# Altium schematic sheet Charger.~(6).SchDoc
size A3; SheetNumber: 2; SheetTotal: 2
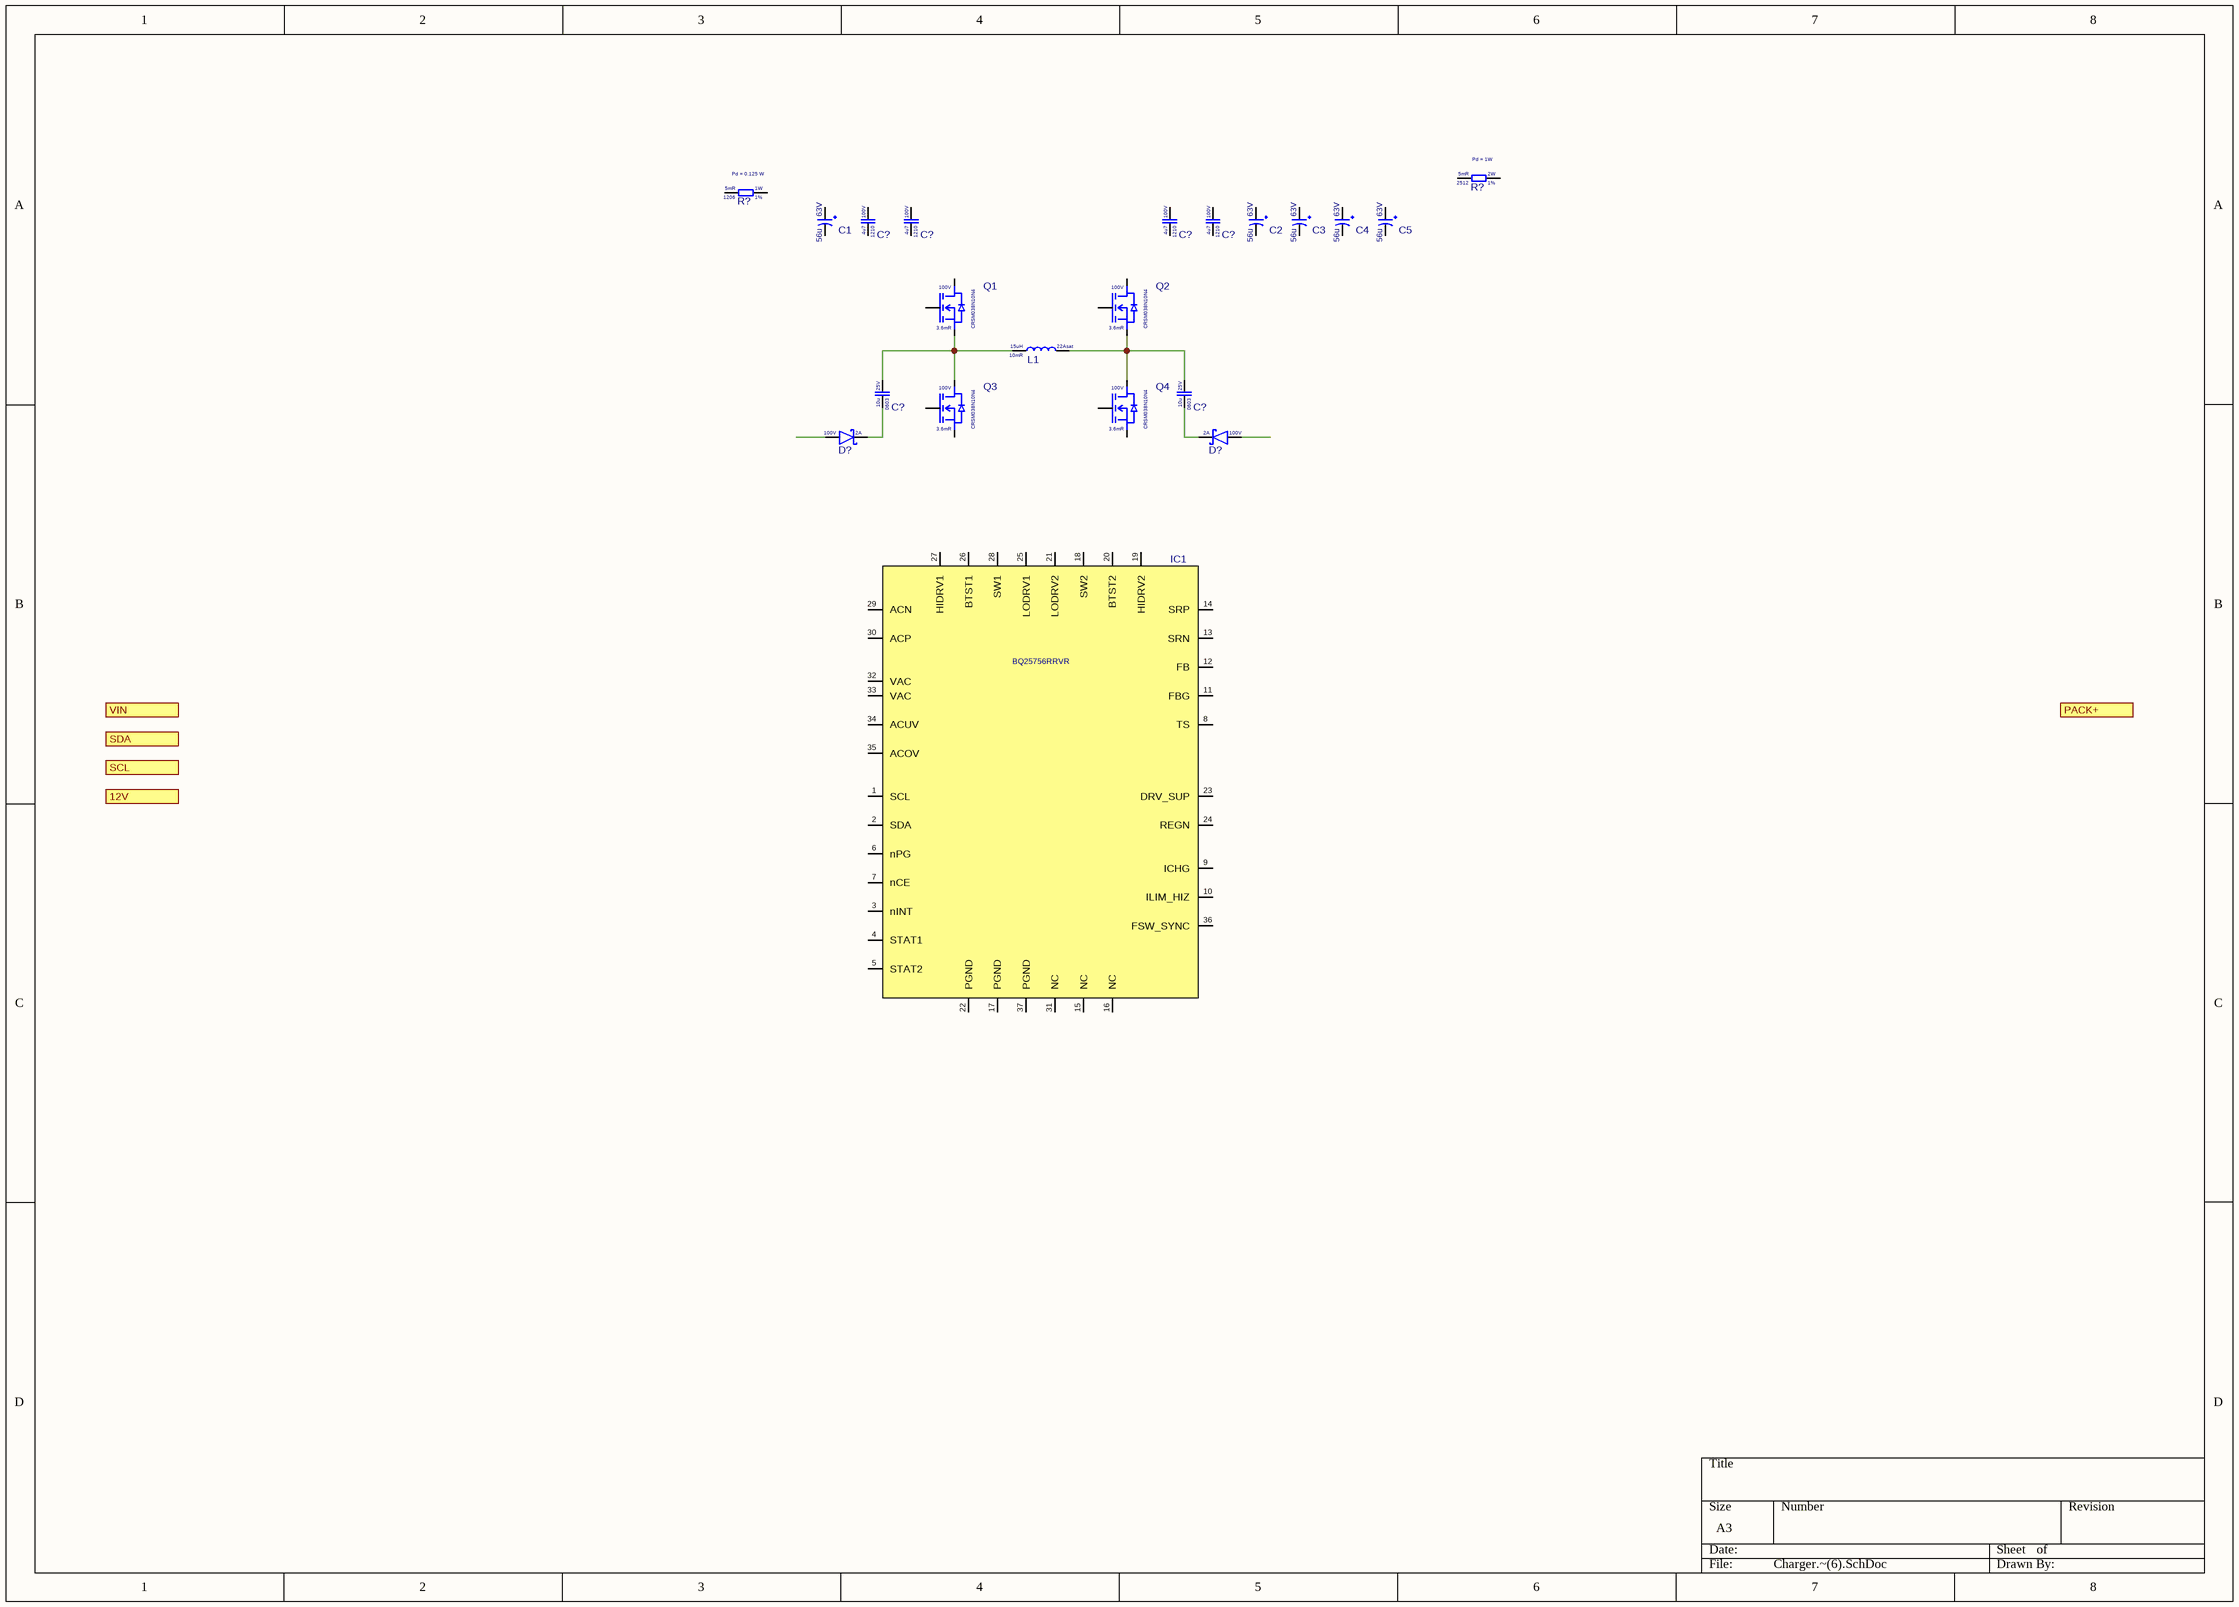
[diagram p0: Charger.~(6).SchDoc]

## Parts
(Parts that share a designator on the sheet are numbered #1, #2 ... from top to bottom, then left to right.)
C1  Voltage Rating: 63V  Capacitance: 56u  [CAP_SMD_10X10.2]  (hidden comment: EEHZA1J560P)
C2  Voltage Rating: 63V  Capacitance: 56u  [CAP_SMD_10X10.2]  (hidden comment: EEHZA1J560P)
C3  Voltage Rating: 63V  Capacitance: 56u  [CAP_SMD_10X10.2]  (hidden comment: EEHZA1J560P)
C4  Voltage Rating: 63V  Capacitance: 56u  [CAP_SMD_10X10.2]  (hidden comment: EEHZA1J560P)
C5  Voltage Rating: 63V  Capacitance: 56u  [CAP_SMD_10X10.2]  (hidden comment: EEHZA1J560P)
C?#1  Voltage Rating: 100V  Case Code (Imperial): 1210  Capacitance: 4u7  [CAP_1210]  (hidden comment: HMK325C7475KN-TE)
C?#2  Voltage Rating: 100V  Case Code (Imperial): 1210  Capacitance: 4u7  [CAP_1210]  (hidden comment: HMK325C7475KN-TE)
C?#3  Voltage Rating: 100V  Case Code (Imperial): 1210  Capacitance: 4u7  [CAP_1210]  (hidden comment: HMK325C7475KN-TE)
C?#4  Voltage Rating: 100V  Case Code (Imperial): 1210  Capacitance: 4u7  [CAP_1210]  (hidden comment: HMK325C7475KN-TE)
C?#5  Voltage Rating: 25V  Case Code (Imperial): 0603  Capacitance: 10u  [CAP 0603]  (hidden comment: CL10A106MA8NRNC)
C?#6  Voltage Rating: 25V  Case Code (Imperial): 0603  Capacitance: 10u  [CAP 0603]  (hidden comment: CL10A106MA8NRNC)
D?#1  Forward Current: 2A  Reverse Voltage: 100V  [SMAF]  (hidden comment: SS210F)
D?#2  Forward Current: 2A  Reverse Voltage: 100V  [SMAF]  (hidden comment: SS210F)
IC1  BQ25756RRVR  [VQFN-36(5x6)]
L1  Resistance: 10mR  Saturation current: 22Asat  Inductance: 15uH  [MTF1810-150M]  (hidden comment: MTF1810-150M)
Q1  Rds: 3.6mR  Voltage: 100V  [DFN-8 (5x6)]  (hidden comment: CRSM038N10N4)
Q2  Rds: 3.6mR  Voltage: 100V  [DFN-8 (5x6)]  (hidden comment: CRSM038N10N4)
Q3  Rds: 3.6mR  Voltage: 100V  [DFN-8 (5x6)]  (hidden comment: CRSM038N10N4)
Q4  Rds: 3.6mR  Voltage: 100V  [DFN-8 (5x6)]  (hidden comment: CRSM038N10N4)
R?#1  Pd = 1W  Resistance Tolerance: 1%  Resistance: 5mR  Power Rating: 2W  Case Code (Imperial): 2512  [RES_2512]
R?#2  Pd = 0.125 W  Resistance Tolerance: 1%  Resistance: 5mR  Power Rating: 1W  Case Code (Imperial): 1206  [RES_1206]

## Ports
12V (see Arhitecture[5B]), PACK+ (see Arhitecture[6B]), SCL (see Arhitecture[5B]), SDA (see Arhitecture[5B]), VIN (see Arhitecture[5B])

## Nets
NetC?#5_1: C?#5.1 D?#1.K
NetC?#5_2: C?#5.2 L1.1 Q1.S Q3.D
NetC?#6_1: C?#6.1 D?#2.K
NetC?#6_2: C?#6.2 L1.2 Q2.S Q4.D

Not connected (* = marked no-connect by the designer): C1 + -; C2 + -; C3 + -; C4 + -; C5 + -; C?#1 1 2; C?#2 1 2; C?#3 1 2; C?#4 1 2; D?#1 A; D?#2 A; IC1 1(SCL) 2(SDA) 3(nINT) 4(STAT1) 5(STAT2) 6(nPG) 7(nCE) 8(TS) 9(ICHG) 10(ILIM_HIZ) 11(FBG) 12(FB) 13(SRN) 14(SRP) 15(NC) 16(NC) 17(PGND) 18(SW2) 19(HIDRV2) 20(BTST2) 21(LODRV2) 22(PGND) 23(DRV_SUP) 24(REGN) 25(LODRV1) 26(BTST1) 27(HIDRV1) 28(SW1) 29(ACN) 30(ACP) 31(NC) 32(VAC) 33(VAC) 34(ACUV) 35(ACOV) 36(FSW_SYNC) 37(PGND); Q1 D G; Q2 D G; Q3 G S; Q4 G S; R?#1 1 2; R?#2 1 2

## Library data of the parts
C1-C5 = EEHZA1J560P: Cap AL-EL 56uF 63V 30mR 1.8Ar SMD 10x10.2mm; Manufacturer: Panasonic
C?#1-C?#4 = HMK325C7475KN-TE: Cap 4.7uF 100V 1210 X7R; Manufacturer: Taiyo Yuden
C?#5 C?#6 = CL10A106MA8NRNC: Cap 10uF 25V 0603 X5R; Manufacturer: Samsung
D?#1 D?#2 = SS210F: Schottky 100V 2A 850mVf SMAF; Manufacturer: GOODWORK
IC1 = BQ25756RRVR: Charger IC; Manufacturer: Texas Instruments
L1 = MTF1810-150M: Inductor 15uH 22Asat 10mR SMD 18x18x9 mm; Manufacturer: COILMX
Q1-Q4 = CRSM038N10N4: Nmos 100V 100A 3.6mR DFN-8(5x6); Manufacturer: CRMICRO
R?#1 = RLM25FEER005: Res 5mR 2512 1% 2W; Manufacturer: TA-I Tech
R?#2 = FRM121WFR005TM: Res 5mR 1206 1% 1W; Manufacturer: FOJAN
